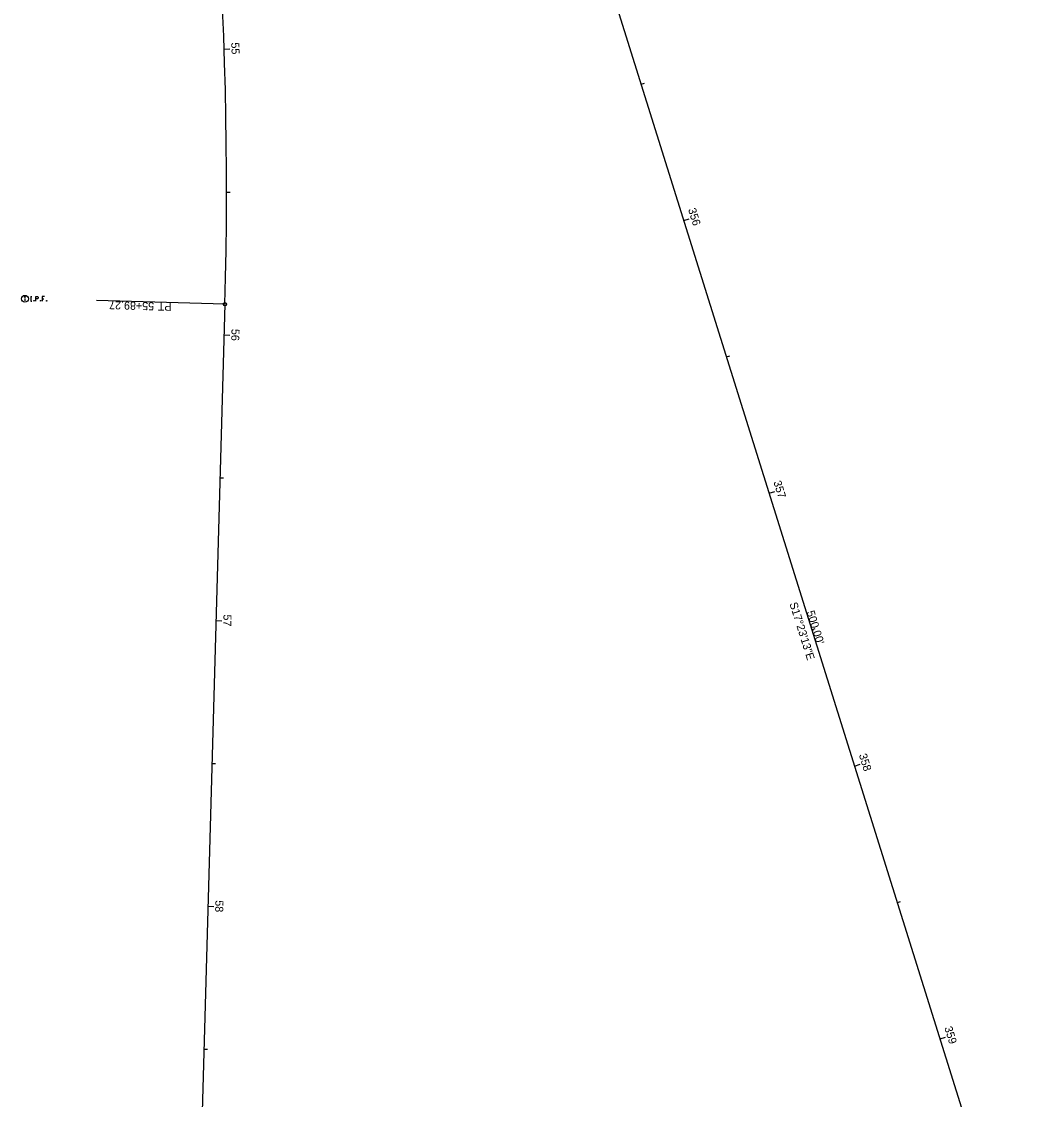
# Model space of a CAD drawing. Extents: x 1918148 to 1920349, y 624677 to 627727.
# Drawn here: x 1918814.9 to 1919166.2, y 626208 to 626585.1 of the extents above; entities that cross this region are included whole.
import ezdxf

# ---------------------------------------------------------------- set-up
doc = ezdxf.new("R2010")
doc.units = 0
for name, color, linetype in [('_CIVIL_CONSTRUCTION', 7, 'Continuous'), ('RS_Raster1', 7, 'Continuous'), ('RW_X_CL', 7, 'Continuous'), ('RW_X_CL_100_Cardinal_Points', 7, 'Continuous'), ('RW_X_CL_100_Curve_Data', 7, 'Continuous'), ('SV_X_Mon_Cells_Found', 7, 'Continuous')]:
    doc.layers.add(name, color=color, linetype=linetype)

msp = doc.modelspace()

# ---------------------------------------------------------------- linework, layer by layer
at = {"layer": 'RS_Raster1'}
for p, q in [((1919016.77, 626610.92), (1919166.18, 626133.77)), ((1918886.1, 626486.21), (1918868.79, 625871.19))]:
    msp.add_line(p, q, dxfattribs=at)
msp.add_arc((1917456.28, 626526.45), 1430.39, 358.38778, 10.40444, dxfattribs=at)
at = {"layer": 'RW_X_CL'}
msp.add_line((1918886.1, 626486.21), (1918841.12, 626487.47), dxfattribs=at)
msp.add_circle((1918886.1, 626486.21), 0.6, dxfattribs=at)
at = {"layer": 'RW_X_CL_100_Cardinal_Points'}
for p, q in [((1918885.83, 626575.47), (1918887.83, 626575.53)), ((1919031.71, 626563.21), (1919032.85, 626563.57)), ((1918886.67, 626525.48), (1918887.87, 626525.47)), ((1919046.65, 626515.49), (1919048.56, 626516.09)), ((1918885.8, 626475.48), (1918887.8, 626475.43)), ((1919061.59, 626467.78), (1919062.74, 626468.13)), ((1918884.39, 626425.5), (1918885.59, 626425.47)), ((1919076.53, 626420.06), (1919078.44, 626420.66)), ((1918882.99, 626375.52), (1918884.99, 626375.47)), ((1919091.47, 626372.34), (1919092.62, 626372.7)), ((1918881.58, 626325.54), (1918882.78, 626325.51)), ((1919106.41, 626324.63), (1919108.32, 626325.23)), ((1919121.36, 626276.91), (1919122.5, 626277.27)), ((1918880.17, 626275.56), (1918882.17, 626275.51)), ((1919136.3, 626229.2), (1919138.21, 626229.8)), ((1918878.77, 626225.58), (1918879.97, 626225.55))]:
    msp.add_line(p, q, dxfattribs=at)
at = {"layer": 'SV_X_Mon_Cells_Found'}
msp.add_line((1918816.14, 626488.24), (1918816.14, 626487.36), dxfattribs=at)
for points in [[(1918818.17, 626488.92), (1918818.52, 626488.92)], [(1918818.35, 626487.32), (1918818.35, 626488.92)], [(1918819.91, 626487.32), (1918819.91, 626488.92), (1918820.44, 626488.92), (1918820.5, 626488.91), (1918820.57, 626488.89), (1918820.61, 626488.86), (1918820.64, 626488.84), (1918820.68, 626488.77), (1918820.72, 626488.71), (1918820.74, 626488.61), (1918820.74, 626488.46), (1918820.73, 626488.41), (1918820.71, 626488.33), (1918820.66, 626488.24), (1918820.62, 626488.21), (1918820.58, 626488.18), (1918820.53, 626488.16), (1918820.44, 626488.14), (1918819.91, 626488.14)], [(1918822.92, 626488.92), (1918822.16, 626488.92), (1918822.16, 626487.32)], [(1918818.17, 626487.32), (1918818.52, 626487.32)], [(1918819.31, 626487.54), (1918819.36, 626487.54), (1918819.39, 626487.51), (1918819.43, 626487.46), (1918819.43, 626487.4), (1918819.39, 626487.35), (1918819.36, 626487.32), (1918819.31, 626487.32), (1918819.27, 626487.35), (1918819.24, 626487.4), (1918819.24, 626487.46), (1918819.27, 626487.51), (1918819.31, 626487.54)], [(1918821.55, 626487.54), (1918821.61, 626487.54), (1918821.64, 626487.51), (1918821.68, 626487.46), (1918821.68, 626487.4), (1918821.64, 626487.35), (1918821.61, 626487.32), (1918821.55, 626487.32), (1918821.52, 626487.35), (1918821.49, 626487.4), (1918821.49, 626487.46), (1918821.52, 626487.51), (1918821.55, 626487.54)], [(1918822.16, 626488.14), (1918822.7, 626488.14)], [(1918823.7, 626487.54), (1918823.76, 626487.54), (1918823.79, 626487.51), (1918823.83, 626487.46), (1918823.83, 626487.4), (1918823.79, 626487.35), (1918823.76, 626487.32), (1918823.7, 626487.32), (1918823.67, 626487.35), (1918823.64, 626487.4), (1918823.64, 626487.46), (1918823.67, 626487.51), (1918823.7, 626487.54)]]:
    msp.add_lwpolyline(points, dxfattribs=at)
for centre, radius in [((1918816.14, 626488.12), 1.2), ((1918816.14, 626488.78), 0.16)]:
    msp.add_circle(centre, radius, dxfattribs=at)

# ---------------------------------------------------------------- texts
at = {"layer": '_CIVIL_CONSTRUCTION'}
msp.add_text('S17°23\'13"E', height=2.8, rotation=287.387, dxfattribs=at).set_placement((1919083.58, 626381.48))
at = {"layer": 'RW_X_CL'}
for s, p in [('55+89.27', (1918861.35, 626486.86)), ('PT', (1918867.44, 626486.69))]:
    msp.add_text(s, height=2.8, rotation=178.3878, dxfattribs=at).set_placement(p)
at = {"layer": 'RW_X_CL_100_Cardinal_Points'}
for s, rotation, p in [('55', 271.9637, (1918888.3, 626577.76)), ('356', 287.387, (1919048.1, 626519.39)), ('56', 268.3878, (1918888.41, 626477.61)), ('357', 287.387, (1919077.96, 626424.01)), ('57', 268.3878, (1918885.6, 626377.7)), ('358', 287.387, (1919107.87, 626328.52)), ('58', 268.3878, (1918882.78, 626277.68)), ('359', 287.387, (1919137.76, 626233.06))]:
    msp.add_text(s, height=2.8, rotation=rotation, dxfattribs=at).set_placement(p)
at = {"layer": 'RW_X_CL_100_Curve_Data'}
msp.add_text("500.00'", height=2.8, rotation=287.387, dxfattribs=at).set_placement((1919089.58, 626378.55))

doc.saveas('drawing.dxf')
